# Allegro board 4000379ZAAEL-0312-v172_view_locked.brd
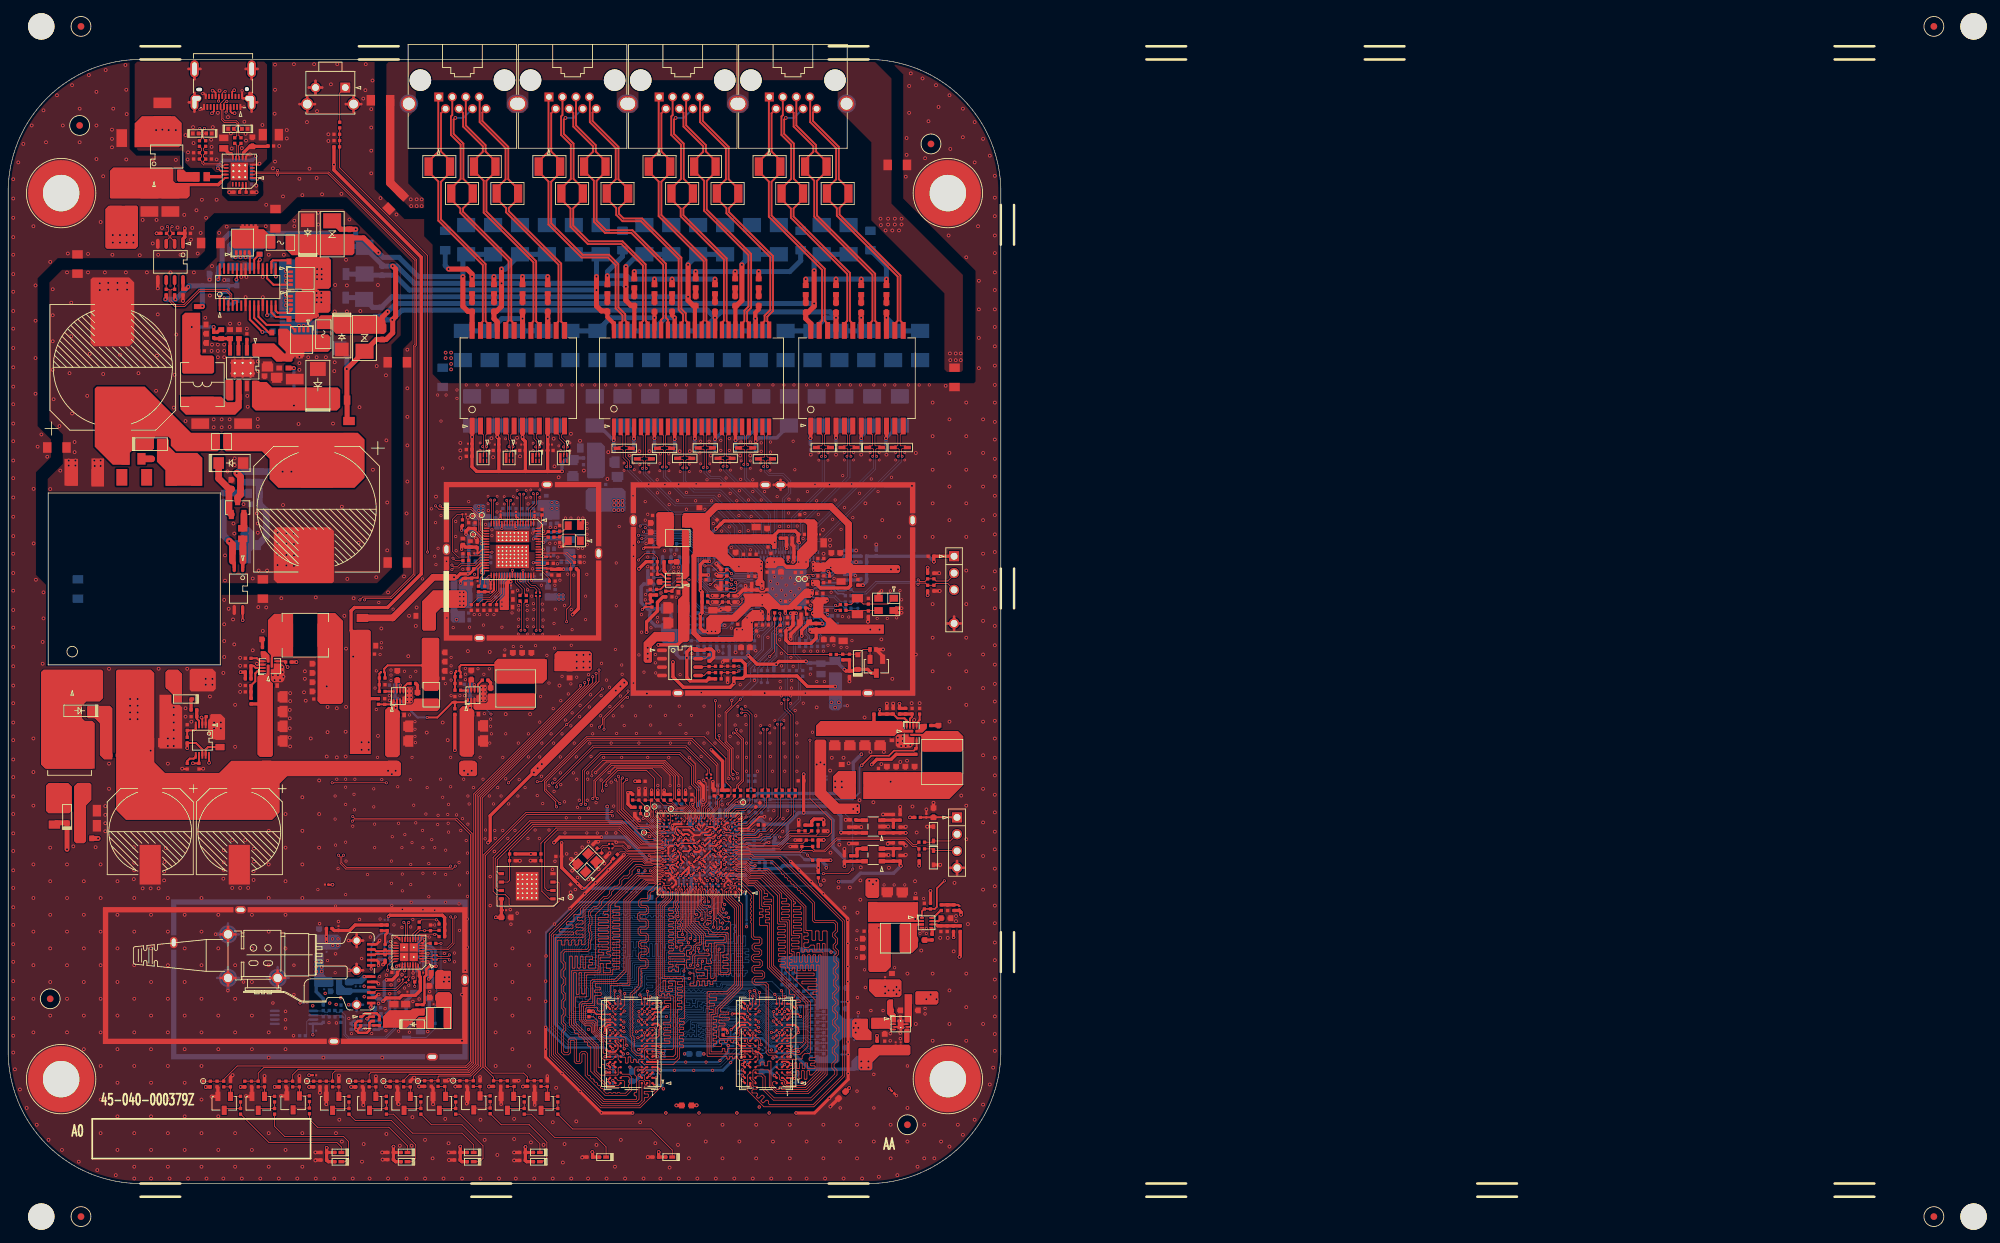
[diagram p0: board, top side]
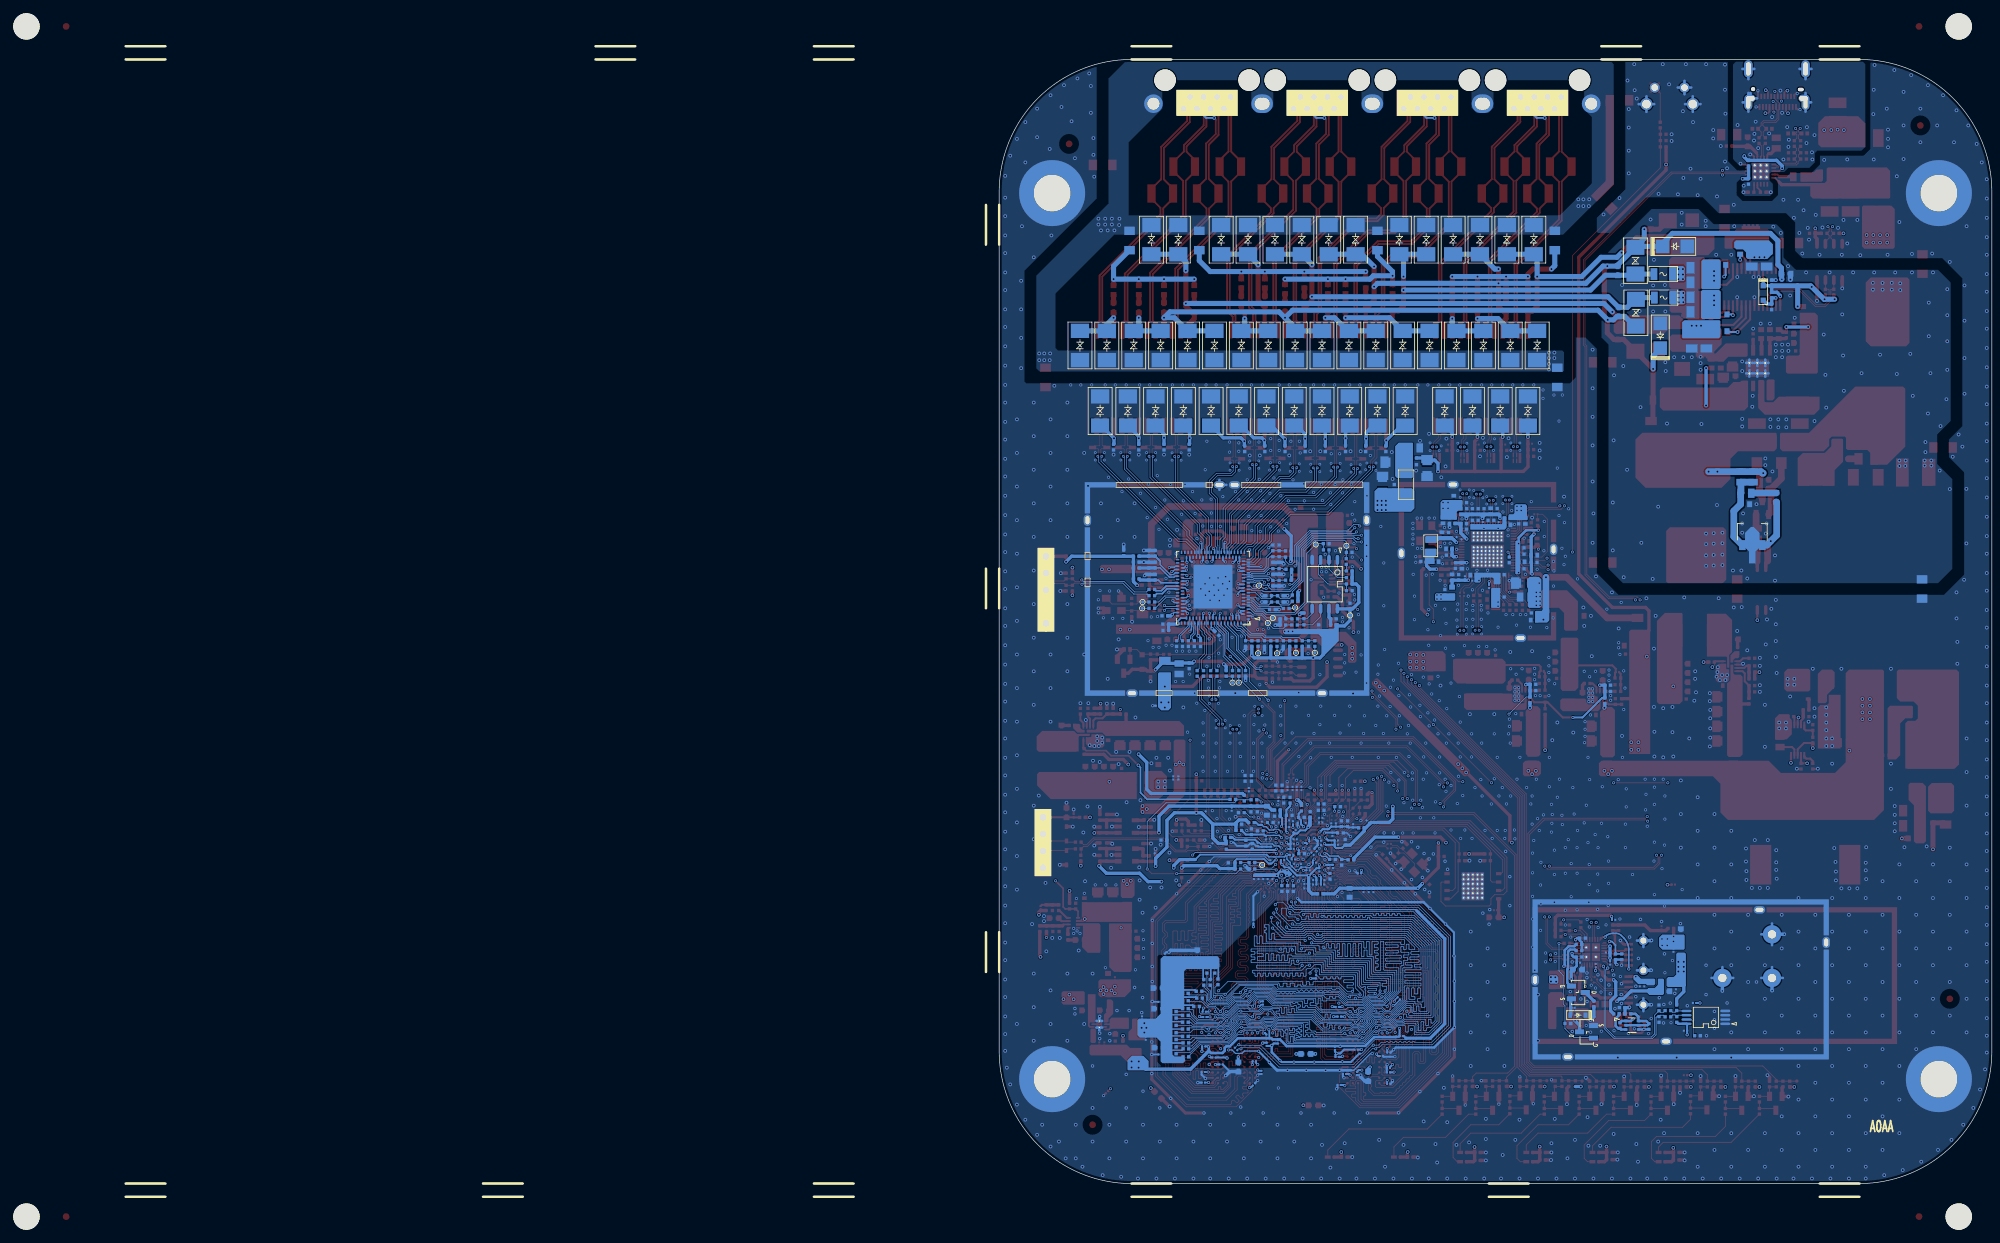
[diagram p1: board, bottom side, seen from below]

Outline 150 x 170 mm; copper layers: TOP, L2, L3, BOTTOM. Coordinates in mm from the lower left corner of the outline.

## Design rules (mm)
constraint set DEFAULT: min track width 0.127
net group DDR_BL0_LDQS: nets DDR_BL0_LDQS_N DDR_BL0_LDQS_P
net group DDR_BL1_UDQS: nets DDR_BL1_UDQS_N DDR_BL1_UDQS_P
net group DDR_BL2_LDQS: nets DDR_BL2_LDQS_N DDR_BL2_LDQS_P
net group DDR_BL3_UDQS: nets DDR_BL3_UDQS_N DDR_BL3_UDQS_P
net group DDR_CK: nets DDR_CK_N DDR_CK_P
net group RXIN_N: nets RXIN1_P RXIN_N
net group RXIN_P: nets RXIN1_N RXIN_P
net group RXOUT+: nets RXOUT+ RXOUTP
net group RXOUT-: nets RXOUT- RXOUTN
net group TXIN_N: nets FXM_P2_TXN TXIN_N
net group TXIN_P: nets FXM_P2_TXP TXIN_P
net group EAR_GND: nets EAR_GND
net group S0RXN: nets N19489844 S0RXN USXGMII1_TD-
net group S0RXP: nets N19489842 S0RXP USXGMII1_TD+
net group S0TXN: nets N19489796 S0TXN USXGMII1_RD-
net group S0TXP: nets N19489794 S0TXP USXGMII1_RD+
net group UART: nets N19665679 N19665693 U0RXD UART0_RX UART0_TX
net group USXGMII0_RD+: nets N17882349 USXGMII0_RD+ USXGMII_TD+_RTL8261BE
net group USXGMII0_RD-: nets N17882351 USXGMII0_RD- USXGMII_TD-_RTL8261BE
net group USXGMII0_TD+: nets N19489360 USXGMII0_TD+ USXGMII_RD+_RTL8261BE
net group USXGMII0_TD-: nets N19489361 USXGMII0_TD- USXGMII_RD-_RTL8261BE

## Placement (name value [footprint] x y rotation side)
C1  10 UF/6.3V  [C0402]  107.97 55.56 0 bottom
C2  0.1 UF/10V  [C0201]  105.73 50.61 180 bottom
C9  10 UF/6.3V  [C0402]  101.35 56.45 180 bottom
C10  10 UF/6.3V  [C0402]  108.2 59.82 90 bottom
C11  10 UF/6.3V  [C0402]  101.35 57.4 180 bottom
C12  10 UF/6.3V  [C0402]  107.25 59.82 90 bottom
C13  10 UF/6.3V  [C0402]  97.35 54.42 90 bottom
C14  10 UF/6.3V  [C0402]  112.84 61.28 90 bottom
C15  0.1 UF/10V  [C0201]  107.82 58.1 270 bottom
C16  10 UF/6.3V  [C0402]  83.19 49.47 180 top
C17  0.1 UF/100V  [C0603]  16 64.77 180 top
C18  10 UF/6.3V  [C0402]  95.82 60.83 0 top
C19  10 UF/6.3V  [C0402]  111.95 56.64 270 bottom
C20  10 UF/6.3V  [C0402]  111 56.64 270 bottom
C21  10 UF/6.3V  [C0402]  85.28 45.53 225 top
C22  10 UF/6.3V  [C0402]  125.12 51.94 0 bottom
C23  10 UF/6.3V  [C0402]  113.79 54.36 180 bottom
C24  0.1 UF/10V  [C0201]  102.11 31.26 270 bottom
C25  0.1 UF/10V  [C0201]  94.16 44.32 270 bottom
C26  0.1 UF/10V  [C0201]  93.45 44.32 270 bottom
C27  0.1 UF/10V  [C0201]  94.95 44.32 270 bottom
C28  0.1 UF/10V  [C0201]  138.75 55.63 90 top
C29  82 PF/50V  [C0402]  28.83 63.12 270 top
C86  0.1 UF/16V  [C0402]  113.92 59.05 270 top
C87  0.1 UF/16V  [C0402]  114.87 59.05 270 top
C89  0.1 UF/16V  [C0402]  117.98 59.05 270 top
C93  0.1 UF/16V  [C0402]  118.94 59.05 270 top
C94  0.1 UF/10V  [C0201]  119.17 15.27 0 bottom
C95  0.01 UF/16V  [C0201]  110.38 16.81 270 bottom
C96  6800 PF/10V  [C0201]  109.58 21.06 270 bottom
C98  0.1 UF/10V  [C0201]  109.63 22.29 90 bottom
C99  4700 PF/10V  [C0201]  117.54 19.05 180 bottom
C100  6800 PF/10V  [C0201]  95.55 46.91 0 bottom
C101  1 UF/6.3V  [C0201]  119.09 20.73 0 bottom
C102  2200 PF/16V  [C0201]  110.15 27.31 90 bottom
C103  1500 PF/16V  [C0201]  119.02 25.98 0 bottom
C104  1500 PF/16V  [C0201]  118.91 25.18 0 bottom
C105  1000 PF/50V  [C0201]  111.44 18.5 0 bottom
C106  2200 PF/16V  [C0201]  91.11 19.81 180 bottom
C110  4700 PF/10V  [C0201]  91.19 16.81 0 bottom
C111  0.1 UF/10V  [C0201]  99.26 20.45 270 bottom
C112  1500 PF/16V  [C0201]  91.19 17.48 0 bottom
C113  1000 PF/50V  [C0201]  98.6 25.25 0 bottom
C114  1500 PF/16V  [C0201]  111.58 39.57 90 bottom
C115  0.01 UF/16V  [C0201]  89.61 28.02 45 bottom
C116  0.1 UF/10V  [C0201]  133.71 13.82 315 top
C117  1 UF/6.3V  [C0201]  104.39 48.06 90 bottom
C136  1 UF/16V  [C0402]  69.66 111 180 top
C137  1 UF/16V  [C0402]  81.92 110.87 0 top
C139  1 UF/16V  [C0402]  128.91 111.38 270 bottom
C140  1 UF/6.3V  [C0201]  92.26 19.28 180 bottom
C141  0.1 UF/10V  [C0201]  95.94 16.64 270 bottom
C142  1 UF/6.3V  [C0201]  116.47 18.01 180 bottom
C143  10 UF/6.3V  [C0603]  125.98 29.57 0 bottom
C144  10 UF/6.3V  [C0603]  120.07 34.6 90 bottom
C145  10 UF/6.3V  [C0603]  125.91 26.44 0 bottom
C146  10 UF/6.3V  [C0603]  125.83 20.55 0 bottom
C148  1 UF/16V  [C0402]  73.72 110.87 180 top
C151  1 UF/16V  [C0402]  77.72 110.87 180 top
C153  0.01 UF/16V  [C0201]  105.79 49.72 180 bottom
C154  0.1 UF/10V  [C0201]  105.61 48.16 135 bottom
C155  0.1 UF/10V  [C0201]  102.36 48.51 180 bottom
C156  1 UF/16V  [C0402]  121.28 111.38 270 bottom
C159  0.1 UF/10V  [C0201]  98.91 26.71 0 bottom
C160  1 UF/16V  [C0402]  132.72 111.38 270 bottom
C161  15 PF/50V  [C0402]  89.98 49.68 315 top
C162  15 PF/50V  [C0402]  88.69 50.99 135 top
C166  10 UF/6.3V  [C0402]  98.3 54.42 270 bottom
C167  10 UF/6.3V  [C0402]  107 57.98 270 bottom
C168  0.1 UF/10V  [C0201]  100.25 47.96 270 bottom
C169  0.01 UF/16V  [C0201]  99.57 47.96 270 bottom
C170  0.1 UF/10V  [C0201]  96.52 54.1 270 bottom
C171  0.1 UF/10V  [C0201]  109.41 46.29 270 bottom
C172  0.01 UF/16V  [C0201]  101.14 45.21 180 bottom
C173  10 UF/6.3V  [C0402]  115.38 48.07 90 bottom
C174  0.1 UF/10V  [C0201]  101.41 55.31 180 bottom
C175  0.1 UF/10V  [C0201]  99.12 54.23 270 bottom
C176  0.1 UF/10V  [C0201]  108.71 46.29 270 bottom
C177  0.01 UF/16V  [C0201]  102.31 45.9 0 bottom
C178  10 UF/6.3V  [C0402]  97.71 51.61 90 bottom
C179  0.1 UF/10V  [C0201]  105.28 52.07 0 bottom
C180  0.1 UF/10V  [C0201]  104.65 54.55 180 bottom
C181  10 UF/6.3V  [C0402]  106.17 55.69 180 bottom
C182  0.01 UF/16V  [C0201]  99.82 54.23 270 bottom
C183  0.01 UF/16V  [C0201]  106.43 59.75 90 bottom
C184  0.1 UF/10V  [C0201]  101.12 45.9 180 bottom
C185  0.01 UF/16V  [C0201]  111.51 46.29 270 bottom
C186  0.1 UF/10V  [C0201]  99.06 51.23 180 bottom
C187  0.1 UF/10V  [C0201]  109.7 52.27 90 bottom
C188  0.01 UF/16V  [C0201]  106.43 53.91 180 bottom
C189  10 UF/6.3V  [C0402]  98.42 53.02 180 bottom
C190  0.1 UF/10V  [C0201]  105.74 46.61 225 bottom
C191  0.01 UF/16V  [C0201]  102.31 45.21 0 bottom
C192  0.1 UF/10V  [C0201]  94.3 54.74 45 bottom
C193  0.1 UF/10V  [C0201]  110.95 51.31 90 bottom
C194  0.01 UF/16V  [C0201]  106.43 54.93 180 bottom
C195  0.1 UF/10V  [C0201]  98.93 19.15 0 bottom
C196  0.01 UF/16V  [C0201]  110.81 46.29 270 bottom
C197  0.01 UF/16V  [C0201]  103.31 51.56 135 bottom
C198  0.01 UF/16V  [C0201]  105.35 53.28 135 bottom
C199  0.1 UF/10V  [C0201]  99.06 51.89 180 bottom
C200  0.1 UF/10V  [C0201]  98.63 14.91 0 bottom
C201  0.01 UF/16V  [C0201]  103.31 47.37 180 bottom
C202  0.01 UF/16V  [C0201]  99.63 52.83 270 bottom
C203  0.01 UF/16V  [C0201]  109.02 48.64 90 bottom
C204  0.1 UF/10V  [C0201]  110.11 46.29 270 bottom
C205  0.01 UF/16V  [C0201]  97.82 16.56 0 bottom
C206  0.01 UF/16V  [C0201]  105.73 51.37 180 bottom
C207  0.01 UF/16V  [C0201]  103.44 54.55 0 bottom
C208  0.1 UF/10V  [C0201]  123.7 61.34 270 bottom
C209  0.01 UF/16V  [C0201]  101.63 51.84 180 bottom
C210  0.01 UF/16V  [C0201]  107.51 54.61 0 bottom
C211  0.1 UF/10V  [C0201]  104.33 59.75 270 bottom
C212  0.01 UF/16V  [C0201]  102.64 49.86 225 bottom
C213  0.01 UF/16V  [C0201]  103.63 44.63 180 bottom
C214  0.1 UF/10V  [C0201]  105.03 59.75 270 bottom
C215  0.01 UF/16V  [C0201]  102.18 50.42 225 bottom
C216  0.01 UF/16V  [C0201]  103.63 45.31 180 bottom
C217  0.1 UF/10V  [C0201]  122.94 61.34 270 bottom
C218  0.01 UF/16V  [C0201]  105.54 49.02 0 bottom
C219  0.01 UF/16V  [C0201]  108.94 50.7 90 bottom
C220  0.1 UF/10V  [C0201]  101.63 47.45 90 bottom
C221  0.1 UF/10V  [C0201]  105.66 59.75 270 bottom
C222  0.01 UF/16V  [C0201]  101.41 54.61 180 bottom
C223  0.1 UF/10V  [C0201]  109.6 50.7 90 bottom
C224  0.1 UF/10V  [C0201]  107.19 48.92 0 bottom
C225  0.1 UF/10V  [C0201]  101.63 51.18 0 bottom
C226  0.01 UF/16V  [C0201]  112.27 59.56 270 bottom
C227  10 UF/6.3V  [C0402]  111.76 51 90 bottom
C228  10 UF/6.3V  [C0402]  99.63 49.02 0 bottom
C229  10 UF/6.3V  [C0402]  104.29 49.88 180 bottom
C230  10 UF/6.3V  [C0402]  111.89 61.28 90 bottom
C231  0.1 UF/10V  [C0201]  110.29 50.7 90 bottom
C232  22 UF/6.3V  [C0603]  126.01 13.39 225 top
C233  1000 PF/2KV  [C1206-0160]  134.37 154.05 0 top
C234  1000 PF/2KV  [C1206-0160]  130.3 142.62 90 bottom
C235  10 UF/6.3V  [C0402]  104.33 55.37 180 bottom
C236  10 UF/6.3V  [C0402]  111.89 53.21 90 bottom
C237  1000 PF/2KV  [C1206-0160]  66.04 142.62 90 bottom
C238  1000 PF/2KV  [C1206-0160]  58.55 148.46 225 top
C239  10 UF/6.3V  [C0402]  112.73 51.49 270 bottom
C241  1000 PF/2KV  [C1206-0160]  56.26 163.83 180 top
C242  0.01 UF/100V  [C0603]  81.53 132.59 90 top
C243  0.01 UF/100V  [C0603]  77.72 132.59 90 top
C244  0.01 UF/100V  [C0603]  73.41 132.59 90 top
C245  0.01 UF/100V  [C0603]  70.1 132.59 90 top
C246  0.01 UF/100V  [C0603]  132.72 132.46 90 top
C247  0.01 UF/100V  [C0603]  128.91 132.46 90 top
C248  0.01 UF/100V  [C0603]  125.09 132.46 90 top
C249  0.01 UF/100V  [C0603]  120.52 132.46 90 top
C250  0.01 UF/100V  [C0603]  113.41 133.48 90 top
C251  0.01 UF/100V  [C0603]  109.86 133.48 90 top
C252  0.01 UF/100V  [C0603]  94.61 133.48 90 top
C253  0.01 UF/100V  [C0603]  103.89 133.48 90 top
C254  0.01 UF/100V  [C0603]  100.33 132.59 90 top
C255  1 UF/6.3V  [C0402]  33.27 132.59 270 bottom
C256  0.01 UF/100V  [C0603]  97.66 132.59 90 top
C257  0.01 UF/100V  [C0603]  106.81 132.59 90 top
C258  0.01 UF/100V  [C0603]  90.55 132.59 90 top
C259  1000 PF/2KV  [C1206-0160]  143 121.92 270 top
C260  1000 PF/2KV  [C1206-0160]  40.39 145.92 90 top
C261  1000 PF/2KV  [C1206-0160]  58.8 124.21 0 top
C262  1000 PF/2KV  [C1206-0160]  58.8 93.92 0 top
C263  1000 PF/2KV  [C1206-0160]  38.48 89.92 90 top
C264  1000 PF/2KV  [C1206-0160]  30.61 142.24 180 top
C265  1000 PF/2KV  [C1206-0160]  10.54 89.92 270 bottom
C266  1000 PF/2KV  [C1206-0160]  7.37 111.32 180 top
C267  1000 PF/2KV  [C1206-0160]  10.48 139.06 90 top
C270  0.1 UF/10V  [C0201]  105.54 61.59 90 top
C271  0.1 UF/10V  [C0201]  106.24 61.59 90 top
C272  2.2 UF/6.3V  [C0402]  111.81 47.57 0 bottom
C276  1 UF/16V  [C0402]  125.09 111.38 270 bottom
C277  0.1 UF/10V  [C0201]  74.99 41.34 0 top
C278  10 UF/6.3V  [C0603]  75.25 40.26 0 top
C279  1 UF/16V  [C0402]  97.66 111.12 270 bottom
C280  1 UF/16V  [C0402]  91.57 111.12 270 bottom
C281  1 UF/16V  [C0402]  100.71 111.12 270 bottom
C282  1 UF/16V  [C0402]  94.61 111.12 270 bottom
C283  1 UF/16V  [C0402]  109.86 111.12 270 bottom
C284  1 UF/16V  [C0402]  103.76 111.12 270 bottom
C285  1 UF/16V  [C0402]  112.9 111.12 270 bottom
C286  1 UF/16V  [C0402]  106.81 111.12 270 bottom
C288  1000 PF/2KV  [C1206-0160]  119.76 142.62 90 bottom
C293  1000 PF/2KV  [C1206-0160]  65.66 121.92 270 bottom
C294  1000 PF/2KV  [C1206-0160]  92.84 142.62 90 bottom
C600  0.1 UF/10V  [C0201]  60.32 30.58 225 top
C601  0.1 UF/10V  [C0201]  59.82 31.05 225 top
C602  0.01 UF/16V  [C0201]  59.84 32.96 90 bottom
C603  0.01 UF/50V  [C0402]  58.4 31.94 180 top
C606  0.1 UF/10V  [C0201]  62.47 31.9 0 top
C607  0.1 UF/10V  [C0201]  49.91 38.67 90 top
C608  0.1 UF/10V  [C0201]  58.07 34.92 0 bottom
C609  0.1 UF/10V  [C0201]  64.51 33.86 180 top
C610  0.1 UF/10V  [C0201]  64.51 34.54 180 top
C611  6.2 PF/50V  [C0402]  62.39 34.26 180 bottom
C612  0.1 UF/50V  [C0402]  55.86 26.61 180 bottom
C613  1 UF/6.3V  [C0201]  52.52 30.07 270 bottom
C614  0.1 UF/10V  [C0201]  53.19 30.07 270 bottom
C616  0.1 UF/10V  [C0201]  46.28 23.11 0 bottom
C619  1 UF/50V  [C0805]  58.29 26.34 90 top
C620  2.2 UF/50V  [C0805]  60.07 26.34 90 top
C621  4.7 PF/50V  [C0402]  61.77 26.63 90 top
C623  10 UF/6.3V  [C0603]  49.42 29.08 180 bottom
C624  0.1 UF/10V  [C0201]  60.33 28.77 90 top
C625  10 UF/6.3V  [C0603]  62.61 32.35 180 bottom
C626  0.1 UF/10V  [C0201]  62.45 33.4 180 bottom
C631  10 UF/6.3V  [C0603]  64.35 29.89 180 top
C632  0.1 UF/10V  [C0201]  47.74 29.63 270 bottom
C633  0.1 UF/10V  [C0201]  46.29 16.38 0 top
C634  0.1 UF/10V  [C0201]  126.1 72.26 0 bottom
C635  0.1 UF/10V  [C0201]  44.92 27.31 0 bottom
C636  0.1 UF/10V  [C0201]  48.12 45.21 180 top
C637  0.1 UF/10V  [C0201]  57.15 39.88 180 bottom
C638  10 UF/6.3V  [C0603]  64.41 28.13 180 top
C639  0.1 UF/10V  [C0201]  64.52 27.11 180 top
C640  0.1 UF/10V  [C0201]  57.68 33.36 270 bottom
C643  10 UF/6.3V  [C0603]  46.99 37.78 90 bottom
C644  0.1 UF/10V  [C0201]  48.11 35.29 270 bottom
C719  0.1 UF/16V  [C0402]  27.11 143.7 0 top
C720  0.1 UF/16V  [C0402]  26.42 134.81 90 top
C810  0.1 UF/16V  [C0402]  49.66 158.69 180 top
C843  0.1 UF/100V  [C0603]  34.23 118.94 0 top
C844  2.2 UF/100V  [C1210]  43.31 120.27 90 top
C845  1 UF/100V  [C1206]  40.58 120.65 90 top
C846  0.1 UF/100V  [C0603]  38.73 121.41 90 top
C847  680 PF/50V  [C0402]  31.05 128.33 270 top
C848  0.1 UF/16V  [C0402]  29.21 125.92 0 top
C849  22 UF/10V  [C0603]  29.21 127.13 0 top
C850  22 UF/10V  [C0603]  29.21 128.52 0 top
C851  1 UF/100V  [C1206]  39.18 124.78 270 top
C852  1 UF/16V  [C0402]  36.07 128.08 90 top
C911  1000 PF/50V  [C0402]  54.93 80.07 0 top
C922  0.1 UF/10V  [C0201]  117.6 51.64 315 bottom
C925  10 UF/6.3V  [C0603]  139.83 56.07 90 top
C926  0.1 UF/10V  [C0201]  126.31 49.78 45 bottom
C927  0.1 UF/10V  [C0201]  118.97 56.11 135 bottom
C928  0.1 UF/10V  [C0201]  132.51 30.96 90 top
C944  10 UF/6.3V  [C0603]  136.78 26.19 0 top
C946  10 UF/6.3V  [C0603]  134.11 26.19 0 top
C947  10 UF/6.3V  [C0603]  132.46 23.32 270 top
C948  0.1 UF/10V  [C0201]  134.11 21.11 90 top
C949  0.1 UF/10V  [C0201]  134.87 21.11 90 top
C956  470 PF/50V  [C0201]  89.25 22.3 180 bottom
C957  470 PF/50V  [C0201]  107.9 21.42 270 bottom
C958  1000 PF/50V  [C0201]  119.17 16.87 0 bottom
C959  1000 PF/50V  [C0201]  96.06 20.24 0 bottom
C960  3300 PF/16V  [C0201]  111.5 14.99 135 bottom
C961  3300 PF/16V  [C0201]  91.12 15.07 180 bottom
C971  10 UF/6.3V  [C0603]  103.66 19.6 0 bottom
C972  10 UF/6.3V  [C0603]  94.25 16.19 270 bottom
C973  10 UF/6.3V  [C0603]  102.51 11.81 180 top
C974  10 UF/6.3V  [C0603]  113.85 17.61 270 bottom
C976  0.1 UF/10V  [C0201]  128.42 25.03 90 bottom
C977  0.1 UF/10V  [C0201]  127.86 21.98 270 bottom
C978  470 PF/50V/10%  [C0201]  125.68 27.48 0 bottom
C979  1 UF/6.3V  [C0201]  124.97 34.52 90 bottom
C980  1 UF/6.3V  [C0201]  125.68 19.52 0 bottom
C981  0.1 UF/16V  [C0402]  49.66 157.73 0 top
C1002  0.22 UF/6.3V  [C0402]  134.79 51.09 90 top
C1003  1 UF/6.3V  [C0402]  134.79 49.19 90 top
C1004  1 UF/6.3V  [C0402]  119.81 60.91 180 top
C1005  1 UF/6.3V  [C0402]  126.36 49.15 90 top
C1006  0.022 UF/25V  [C0402]  127.32 49.15 90 top
C1007  0.22 UF/6.3V  [C0402]  134.79 55.38 90 top
C1008  1 UF/6.3V  [C0402]  134.79 53.48 90 top
C1009  1 UF/6.3V  [C0402]  127.04 53.48 90 top
C1010  1 UF/6.3V  [C0402]  128.05 53.48 90 top
C1011  0.01 UF/50V  [C0402]  127.67 55 180 top
C1012  0.1 UF/10V  [C0201]  114.87 56.63 270 bottom
C1013  0.01 UF/16V  [C0201]  105.6 54.55 90 bottom
C1014  0.01 UF/16V  [C0201]  110.3 54.48 90 bottom
C8557  1 UF/50V  [C0805]  32.58 157.35 90 top
C8558  0.1 UF/50V  [C0603]  36.89 157.54 90 top
C8559  10 UF/50V  [C1210]  24.51 148.4 270 top
C8560  10 UF/50V  [C1210]  23.3 162.05 90 top
C8561  10 UF/50V  [C1210]  21.34 148.4 270 top
C8562  10 UF/50V  [C1210]  18.54 158.12 180 top
C8564  10 UF/50V  [C1210]  22.35 69.22 0 top
C8565  1 UF/50V  [C0805]  22.35 66.67 0 top
C8566  0.22 UF/16V  [C0402]  27.05 63.12 270 top
C8567  10 UF/50V  [C1210]  22.35 72.52 0 top
C8568  4.7 UF/25V  [C0805]  32 66.8 90 top
C8569  220 UF/100V  [CES-1800-P-1750-S]  15.81 123.44 90 top
C8571  0.1 UF/100V  [C0603]  34.42 106.43 180 top
C8572  0.1 UF/16V  [C0402]  33.27 136.21 270 bottom
C8573  0.1 UF/100V  [C0603]  31.11 137.6 180 bottom
C8574  0.1 UF/100V  [C0603]  56.52 128.33 90 top
C8575  0.1 UF/100V  [C0603]  56.39 131.83 90 bottom
C8576  0.1 UF/100V  [C0603]  56.52 138.05 270 bottom
C8577  0.1 UF/100V  [C0603]  51.56 143.64 270 top
C8578  220 PF/100V  [C0805]  36.07 106.87 270 bottom
C8580  100 PF/100V  [C0603]  22.35 109.6 180 top
C8581  2.2 UF/100V  [C1210]  29.02 113.54 90 top
C8582  0.22 UF/25V  [C0603]  32.58 103.76 90 bottom
C8583  2.2 UF/100V  [C1210]  35.5 113.54 90 top
C8584  220 UF/100V  [CES-1800-P-1750-S]  46.61 101.98 270 top
C8585  220 UF/63V  [CES-1250-P-1350-L]  21.46 53.21 270 top
C8586  220 UF/63V  [CES-1250-P-1350-L]  34.92 53.21 270 top
C8595  330 PF/50V  [C0402]  30.29 155.89 0 top
C8596  330 PF/50V  [C0402]  28.45 155.89 180 top
CE19  0.1 UF/16V  [C0402]  31.56 15.05 270 top
CE20  0.1 UF/16V  [C0402]  33.59 15.05 90 top
CE21  0.1 UF/16V  [C0402]  38.73 15.05 90 top
CE22  0.1 UF/16V  [C0402]  36.77 15.05 270 top
CE23  0.1 UF/16V  [C0402]  44.01 15.05 90 top
CE24  0.1 UF/16V  [C0402]  41.97 15.05 270 top
CE25  0.1 UF/16V  [C0402]  81.47 15.11 90 top
CE26  0.1 UF/16V  [C0402]  79.5 15.11 270 top
CE27  0.1 UF/16V  [C0402]  74.42 15.11 270 top
CE28  0.1 UF/16V  [C0402]  76.45 15.11 90 top
CE29  0.1 UF/16V  [C0402]  47.12 15.05 270 top
CE30  0.1 UF/16V  [C0402]  49.97 15.05 90 top
CE31  0.1 UF/16V  [C0402]  55.56 15.05 90 top
CE32  0.1 UF/16V  [C0402]  58.74 15.05 270 top
CE33  0.1 UF/16V  [C0402]  60.77 15.05 90 top
CE34  0.1 UF/16V  [C0402]  53.53 15.05 270 top
CE35  0.1 UF/16V  [C0402]  65.98 15.11 90 top
CE36  0.1 UF/16V  [C0402]  69.28 15.11 270 top
CE37  0.1 UF/16V  [C0402]  71.31 15.11 90 top
CE38  0.1 UF/16V  [C0402]  63.94 15.11 270 top
CE72  0.1 UF/16V  [C0402]  47.69 4.7 180 top
CE73  0.1 UF/16V  [C0402]  47.69 3.56 180 top
CE74  0.1 UF/16V  [C0402]  57.78 4.7 180 top
CE75  0.1 UF/16V  [C0402]  97.85 4 180 top
CE76  0.1 UF/16V  [C0402]  87.88 4 180 top
CE77  0.1 UF/16V  [C0402]  57.78 3.62 180 top
CE78  0.1 UF/16V  [C0402]  67.88 3.56 180 top
CE79  0.1 UF/16V  [C0402]  67.88 4.7 180 top
CE80  0.1 UF/16V  [C0402]  77.72 3.49 180 top
CE81  0.1 UF/16V  [C0402]  77.72 4.7 180 top
D3  SCS4148LWS-C  [DOS-SOD-323L-SECOS]  34.54 134.68 270 bottom
D65  BV-SMBJ58C2  [VARS-SMB-BENCENT]  70.1 116.84 270 bottom
D66  BV-SMBJ58C2  [VARS-SMB-BENCENT]  74.3 116.84 270 bottom
D67  BV-SMBJ58C2  [VARS-SMB-BENCENT]  78.49 116.84 270 bottom
D68  BV-SMBJ58C2  [VARS-SMB-BENCENT]  82.68 116.84 270 bottom
D69  BV-SMBJ58C2  [VARS-SMB-BENCENT]  122.17 116.84 270 bottom
D70  BV-SMBJ58C2  [VARS-SMB-BENCENT]  130.56 116.84 270 bottom
D71  BV-SMBJ58C2  [VARS-SMB-BENCENT]  134.75 116.84 270 bottom
D72  BV-SMBJ58C2  [VARS-SMB-BENCENT]  126.36 116.84 270 bottom
D73  BV03C-H  [VARS-SOD-323-BENCENT]  134.81 111.32 0 top
D74  BV03C-H  [VARS-SOD-323-BENCENT]  130.94 111.32 0 top
D75  BV03C-H  [VARS-SOD-323-BENCENT]  127.06 111.32 0 top
D76  BV03C-H  [VARS-SOD-323-BENCENT]  123.19 111.32 0 top
D77  BV-SMBJ58C2  [VARS-SMB-BENCENT]  88.65 116.84 270 bottom
D78  BV-SMBJ58C2  [VARS-SMB-BENCENT]  97.03 116.84 270 bottom
D79  BV-SMBJ58C2  [VARS-SMB-BENCENT]  68.71 126.75 270 bottom
D80  BV-SMBJ58C2  [VARS-SMB-BENCENT]  81.41 142.75 90 bottom
D81  BV-SMBJ58C2  [VARS-SMB-BENCENT]  80.9 126.75 270 bottom
D82  BV-SMBJ58C2  [VARS-SMB-BENCENT]  73.28 142.75 90 bottom
D83  BV-SMBJ58C2  [VARS-SMB-BENCENT]  125.6 126.75 270 bottom
D84  BV-SMBJ58C2  [VARS-SMB-BENCENT]  117.47 126.75 270 bottom
D85  BV-SMBJ58C2  [VARS-SMB-BENCENT]  137.79 126.75 270 bottom
D86  BV-SMBJ58C2  [VARS-SMB-BENCENT]  127 142.75 90 bottom
D87  BV-SMBJ58C2  [VARS-SMB-BENCENT]  101.22 116.84 270 bottom
D88  BV-SMBJ58C2  [VARS-SMB-BENCENT]  92.84 116.84 270 bottom
D89  BV03C-H  [VARS-SOD-323-BENCENT]  102.23 109.66 0 top
D90  BV03C-H  [VARS-SOD-323-BENCENT]  99.19 111.19 0 top
D91  BV03C-H  [VARS-SOD-323-BENCENT]  96.14 109.6 0 top
D92  BV03C-H  [VARS-SOD-323-BENCENT]  93.09 111.19 0 top
D93  BV-SMBJ58C2  [VARS-SMB-BENCENT]  105.41 116.84 270 bottom
D94  BV-SMBJ58C2  [VARS-SMB-BENCENT]  113.79 116.84 270 bottom
D95  BV-SMBJ58C2  [VARS-SMB-BENCENT]  117.98 116.84 270 bottom
D96  BV-SMBJ58C2  [VARS-SMB-BENCENT]  109.6 116.84 270 bottom
D97  BV03C-H  [VARS-SOD-323-BENCENT]  114.43 109.6 0 top
D98  BV03C-H  [VARS-SOD-323-BENCENT]  111.44 111.25 0 top
D99  BV03C-H  [VARS-SOD-323-BENCENT]  108.33 109.66 0 top
D100  BV03C-H  [VARS-SOD-323-BENCENT]  105.35 111.25 0 top
D101  BV-SMBJ58C2  [VARS-SMB-BENCENT]  112.39 142.75 90 bottom
D102  BV-SMBJ58C2  [VARS-SMB-BENCENT]  101.22 126.75 270 bottom
D103  BV-SMBJ58C2  [VARS-SMB-BENCENT]  113.41 126.75 270 bottom
D104  BV-SMBJ58C2  [VARS-SMB-BENCENT]  108.33 142.75 90 bottom
D105  BV-SMBJ58C2  [VARS-SMB-BENCENT]  89.03 126.75 270 bottom
D106  BV-SMBJ58C2  [VARS-SMB-BENCENT]  100.2 142.75 90 bottom
D107  BV-SMBJ58C2  [VARS-SMB-BENCENT]  93.09 126.75 270 bottom
D108  BV-SMBJ58C2  [VARS-SMB-BENCENT]  89.53 142.75 90 bottom
D109  AZ5423-01F.R7GR  [VARS-DFN1006P2E-AMAZING]  33.66 159.51 0 top
D110  AZ5423-01F.R7GR  [VARS-DFN1006P2E-AMAZING]  35.75 159.51 180 top
D111  BV-SMBJ58C2  [VARS-SMB-BENCENT]  76.83 126.75 90 bottom
D112  BV-SMBJ58C2  [VARS-SMB-BENCENT]  72.77 126.75 90 bottom
D113  BV-SMBJ58C2  [VARS-SMB-BENCENT]  77.34 142.75 270 bottom
D114  BV-SMBJ58C2  [VARS-SMB-BENCENT]  69.22 142.75 270 bottom
D115  BV-SMBJ58C2  [VARS-SMB-BENCENT]  133.73 126.75 90 bottom
D116  BV-SMBJ58C2  [VARS-SMB-BENCENT]  129.67 126.75 90 bottom
D117  BV-SMBJ58C2  [VARS-SMB-BENCENT]  121.54 126.75 90 bottom
D118  BV-SMBJ58C2  [VARS-SMB-BENCENT]  122.94 142.75 270 bottom
D119  BV-SMBJ58C2  [VARS-SMB-BENCENT]  109.35 126.75 90 bottom
D120  BV-SMBJ58C2  [VARS-SMB-BENCENT]  116.46 142.75 270 bottom
D121  BV-SMBJ58C2  [VARS-SMB-BENCENT]  105.28 126.75 90 bottom
D122  BV-SMBJ58C2  [VARS-SMB-BENCENT]  104.27 142.75 270 bottom
D123  BV-SMBJ58C2  [VARS-SMB-BENCENT]  97.16 126.75 90 bottom
D124  BV-SMBJ58C2  [VARS-SMB-BENCENT]  84.96 126.75 90 bottom
D125  BV-SMBJ58C2  [VARS-SMB-BENCENT]  96.14 142.75 270 bottom
D126  BV-SMBJ58C2  [VARS-SMB-BENCENT]  85.47 142.75 270 bottom
D127  AZ5423-01F.R7GR  [VARS-DFN1006P2E-AMAZING]  30.35 158.81 180 top
D128  AZ5423-01F.R7GR  [VARS-DFN1006P2E-AMAZING]  28.32 158.81 0 top
D600  SCS4148LWS-C  [DOS-SOD-323-PANJIT]  61.21 24.09 0 top
D601  SCS4148LWS-C  [DOS-SOD-323-PANJIT]  62.55 25.46 0 bottom
D802  LTST-T180TGKT-IM  [LEDS-LTST-T180]  100 4 0 top
D803  LTST-T180TGKT-IM  [LEDS-LTST-T180]  50 4.7 0 top
D804  LTST-T180KEKT-IM  [LEDS-LTST-T180]  60 3.3 0 top
D805  LTST-T180UBKT-IM  [LEDS-LTST-T180]  90 4 0 top
D806  LTST-T180TGKT-IM  [LEDS-LTST-T180]  60 4.7 0 top
D807  BAT54HT1-TH-WS  [DOS-SOD-323-WILLAS]  8.89 55.63 90 top
D808  SS30100HE/100V/3A  [DOS-SOD-123HE-PANJIT]  21.59 111.82 0 top
D809  P6SMBJ58CA  [VARS-SMB-PANJIT]  53.85 127.89 90 top
D810  LTST-T180KEKT-IM  [LEDS-LTST-T180]  50 3.3 0 top
D811  P6SMBJ58CA  [VARS-SMB-PANJIT]  53.78 131.7 90 bottom
D812  BR210_R1_00001  [DOS-SMA-PANJIT]  50.1 128.21 90 bottom
D813  P6SMBJ58CA  [VARS-SMB-PANJIT]  53.85 139.57 270 bottom
D814  P6SMBJ58CA  [VARS-SMB-PANJIT]  48.96 143.57 270 top
D815  1N4148WS  [DOS-SOD-323-GRANDE]  26.67 73.28 180 top
D816  SD101AW/60V/2A  [DOS-SOD-123-PANJIT]  10.79 71.5 180 top
D817  SZAF24A  [DOS-SMA-FL-LRC]  33.66 108.97 0 top
D818  TL431AIPK  [SOT-89-3L-RAC-TI]  36.2 98.55 180 bottom
D819  BR210_R1_00001  [DOS-SMA-PANJIT]  45.28 143.83 90 top
D820  BR210_R1_00001  [DOS-SMA-PANJIT]  47.88 141.73 180 bottom
D821  BR210_R1_00001  [DOS-SMA-PANJIT]  50.42 128.02 270 top
D822  LTST-T180TGKT-IM  [LEDS-LTST-T180]  70 4.7 0 top
D823  LTST-T180KEKT-IM  [LEDS-LTST-T180]  70 3.3 0 top
D824  LTST-T180TGKT-IM  [LEDS-LTST-T180]  80 4.7 0 top
D825  LTST-T180KEKT-IM  [LEDS-LTST-T180]  80 3.3 0 top
D903  PJGBLC24C  [VARS-SOD-323-PANJIT]  139.83 49.28 270 top
D904  PJGBLC24C  [VARS-SOD-323-PANJIT]  139.83 52.9 90 top
E1C1  22 UF/6.3V  [C0805]  87.25 111.25 180 bottom
E1C2  22 UF/6.3V  [C0805]  70.48 88.71 0 bottom
E1C14  1000 PF/25V  [C0402]  69.66 109.98 180 top
E1C16  100 UF/6.3V  [C1206]  85.34 108.2 270 bottom
E1C21  0.1 UF/16V  [C0402]  87.38 108.71 180 bottom
E1C22  220 UF/4V  [C1206]  90.42 109.09 0 bottom
E1C23  0.1 UF/16V  [C0402]  90.3 105.28 90 bottom
E1C24  22 UF/6.3V  [C1206]  92.08 105.66 90 bottom
E1C29  220 UF/4V  [C1206]  70.68 90.81 0 bottom
E1C30  10 UF/10V  [MLCC-0120X0070]  69.85 96.71 90 top
E1C31  10 UF/10V  [MLCC-0120X0070]  75.77 87.18 0 top
E1C32  0.1 UF/16V  [C0402]  75.82 89.47 180 top
E1C33  10 UF/10V  [MLCC-0120X0070]  68.71 97.09 90 top
E1C34  10 UF/10V  [MLCC-0120X0070]  75.82 88.33 0 top
E1C35  10 UF/10V  [MLCC-0120X0070]  83.19 92.46 270 top
E1C36  10 UF/10V  [MLCC-0120X0070]  82.02 95.99 0 bottom
E1C37  0.1 UF/16V  [C0402]  82.14 92.46 90 top
E1C38  0.1 UF/16V  [C0402]  69.09 91.12 90 top
E1C39  1000 PF/50V  [C0201]  79.54 101.34 90 top
E1C40  1000 PF/50V  [C0201]  76.73 101.33 90 top
E1C41  1000 PF/50V  [C0201]  74.42 101.41 90 top
E1C42  0.1 UF/16V  [C0402]  77.62 101.63 270 bottom
E1C43  0.1 UF/16V  [C0402]  79.35 101.63 270 bottom
E1C44  0.1 UF/16V  [C0402]  78.49 101.63 270 bottom
E1C45  1 UF/6.3V  [C0402]  76.73 101.63 90 bottom
E1C46  1 UF/6.3V  [C0402]  74.75 101.66 90 bottom
E1C47  10 UF/10V  [MLCC-0120X0070]  75.73 101.68 270 bottom
E1C48  0.1 UF/16V  [C0402]  79.81 102.98 0 bottom
E1C49  10 UF/10V  [MLCC-0120X0070]  81.31 103.56 270 bottom
E1C50  0.1 UF/16V  [C0402]  70.04 91.12 90 top
E1C51  0.1 UF/16V  [C0402]  70.87 96.58 270 top
E1C52  0.1 UF/16V  [C0402]  81.99 95.03 180 bottom
E1C53  1000 PF/50V  [C0201]  75.97 90.31 90 bottom
E1C54  1000 PF/50V  [C0201]  70.93 91.38 90 top
E1C55  1000 PF/50V  [C0201]  70.68 95.31 0 top
E1C56  1000 PF/50V  [C0201]  81.71 94.8 180 top
E1C57  1000 PF/50V  [C0201]  75.74 90.43 180 top
E1C58  1000 PF/50V  [C0201]  81.38 92.77 90 top
E1C59  1000 PF/50V  [C0201]  74.52 99.8 90 bottom
E1C60  1000 PF/50V  [C0201]  76.91 99.8 90 bottom
E1C61  0.1 UF/16V  [C0402]  77.62 99.88 270 bottom
E1C62  0.1 UF/16V  [C0402]  76.12 99.88 270 bottom
E1C63  0.1 UF/16V  [C0402]  75.26 99.88 270 bottom
E1C64  1 UF/6.3V  [C0402]  78.49 99.88 90 bottom
E1C65  10 UF/10V  [MLCC-0120X0070]  73.18 99.62 0 bottom
E1C66  0.1 UF/16V  [C0402]  71.5 100.2 90 bottom
E1C67  10 UF/10V  [MLCC-0120X0070]  70.48 100.2 90 bottom
E1C68  10 UF/10V  [MLCC-0120X0070]  71.06 94.04 0 bottom
E1C69  10 UF/10V  [MLCC-0120X0070]  80.09 93.45 90 bottom
E1C70  0.1 UF/16V  [C0402]  71.12 95.19 180 bottom
E1C71  0.1 UF/16V  [C0402]  71.12 92.96 180 bottom
E1C72  0.1 UF/16V  [C0402]  81.05 93.45 270 bottom
E1C73  0.1 UF/16V  [C0402]  71.12 96.14 180 bottom
E1C74  1000 PF/50V  [C0201]  73.15 90.61 0 top
E1C75  1000 PF/50V  [C0201]  73.15 89.98 0 top
E1C76  1000 PF/50V  [C0201]  81.05 97.59 135 bottom
E1C77  0.1 UF/16V  [C0402]  82.09 98.05 270 bottom
E1C78  10 UF/10V  [MLCC-0120X0070]  83.08 98.05 270 bottom
E1C79  0.1 UF/16V  [C0402]  85.85 94.09 180 bottom
E1C80  10 UF/10V  [MLCC-0120X0070]  84.05 94.06 0 bottom
E1C81  1000 PF/50V  [C0201]  79.96 97.59 315 bottom
E1C82  0.1 UF/16V  [C0402]  79.81 98.96 0 bottom
E1C83  22 UF/6.3V  [C0402]  79.81 99.8 180 bottom
E1C84  0.1 UF/16V  [C0402]  81.97 100.26 90 bottom
E1C85  10 UF/10V  [MLCC-0120X0070]  82.93 100.31 90 bottom
E1C86  10 UF/10V  [MLCC-0120X0070]  69.22 85.22 180 bottom
E1C87  1 UF/6.3V  [C0402]  69.15 86.3 0 bottom
E1C88  0.1 UF/16V  [C0402]  69.6 99.5 90 top
E1C89  0.1 UF/16V  [C0402]  70.55 99.5 270 top
E1C90  10 UF/10V  [MLCC-0120X0070]  69.15 95 0 bottom
E1C91  1 UF/6.3V  [C0402]  69.91 92.96 180 top
E1C92  0.1 UF/16V  [C0402]  69.15 93.92 180 bottom
E1C93  1000 PF/50V  [C0201]  78.27 91.16 0 bottom
E1C94  0.1 UF/16V  [C0402]  74.12 92.08 180 bottom
E1C95  10 UF/10V  [MLCC-0120X0070]  78.34 92.01 180 bottom
E1C96  1 UF/6.3V  [C0402]  74.12 88.7 180 bottom
E1C97  1000 PF/50V  [C0201]  79.62 91.59 90 bottom
E1C98  0.1 UF/16V  [C0402]  80.57 91.67 90 bottom
E1C99  10 UF/10V  [MLCC-0120X0070]  81.56 91.67 270 bottom
E1C100  1 UF/6.3V  [C0402]  82.65 89.41 90 bottom
E1C149  68 PF/16V  [C0201]  69.72 111.89 180 top
E1C150  68 PF/16V  [C0201]  81.92 111.76 0 top
E1C151  68 PF/16V  [C0201]  77.79 111.76 180 top
E1C152  68 PF/16V  [C0201]  73.79 111.76 180 top
E1FB1  HCB1005KF-121T15  [FILTS-0402]  81.1 100.26 270 bottom
E1L1  2.7 nH/850mA  [L0402]  87.38 109.73 180 bottom
E1L2  PBY321611T-601Y-N  [FILTS-PBY321611T]  88.52 105.66 90 bottom
E1L3  HCB1005KF-121T15  [FILTS-0402]  73.2 100.61 0 bottom
E1L4  1 uH/2.61A Isat  [LS-WIP2016]  84.79 96.45 90 bottom
E1L5  PBY160808T-101Y-N  [FILTS-0603]  81.56 89.51 90 bottom
E1L6  PBY160808T-101Y-N  [FILTS-0603]  74.73 90.38 90 bottom
E1LP1  HCB1005KF-121T15  [FILTS-0402]  80.24 101.63 270 bottom
E1R1  10 OHM  [R0402]  82.04 98.61 180 top
E1R2  10 OHM  [R0402]  82.04 97.74 180 top
E1R3  4.7 K  [R0402]  68.64 99.95 90 top
E1R5  2.49 K  [R0402]  80.69 101.54 270 top
E1R12  1 K  [R0402]  86 93.93 0 top
E1R13  1 K  [R0402]  86 94.82 0 top
E1R14  10 K  [R0402]  81.94 93.81 180 top
E1R15  10 K  [R0402]  72.92 94.32 90 bottom
E1R20  10 K  [R0402]  69.15 95.25 180 top
E1R22  8.2 K  [R0402]  69.15 94.23 0 top
E1R24  1 K  [R0402]  72.01 89.92 90 top
E1R25  1 K  [R0402]  71.06 89.92 90 top
E1R26  1 K  [R0402]  82.22 91.11 180 top
E1R27  1 K  [R0402]  73.79 87.12 270 top
E1R28  1 K  [R0402]  72.83 87.12 270 top
E1R29  1 K  [R0402]  71.88 87.12 270 top
E1R30  1 K  [R0402]  70.93 87.12 270 top
E1R31  1 K  [R0402]  69.98 87.12 270 top
E1U1  RTL8261BE  [QFN68-0800-0400-VIA-10-PH10]  76.2 95.89 270 top
EC16  0.1 UF/16V  [C0402]  105.03 91.31 0 top
EC17  0.1 UF/16V  [C0402]  107.42 100.08 135 top
EC18  0.1 UF/16V  [C0402]  101.73 84.07 90 bottom
EC19  0.1 UF/16V  [C0402]  128.4 90.93 90 top
EC20  0.1 UF/16V  [C0402]  131.19 95.38 90 bottom
EC21  0.1 UF/16V  [C0402]  119.63 100.71 90 top
EC22  0.1 UF/16V  [C0402]  124.97 85.85 0 bottom
EC300  33 PF/50V  [C0402]  83.34 99.09 270 top
EC301  33 PF/50V  [C0402]  83.34 97.36 90 top
EC334  0.1 UF/10V  [C0201]  80.37 89.11 90 top
EC335  0.1 UF/10V  [C0201]  79.76 89.11 90 top
EC340  0.1 UF/10V  [C0201]  68.9 101.22 180 top
ER331  4.7 K  [R0402]  85.45 92.97 180 top
ER359  0 OHM  [R0402]  77.34 88.52 90 top
ER360  0 OHM  [R0402]  78.3 88.52 90 top
EY300  S3225A-050000-F19-CYS-1AMA  [XTALS-0320X0250-YOKE]  85.55 98.35 90 top
F1  1206L150THWR  [FUSES-1206L]  47.62 128.46 270 top
F2  1206L150THWR  [FUSES-1206L]  49.59 133.99 180 bottom
F3  1206L150THWR  [FUSES-1206L]  49.66 137.54 0 bottom
F4  1206L150THWR  [FUSES-1206L]  41.15 142.3 0 top
FB5  BLM15AX601SN1D  [FILTS-0402]  115.44 52.35 180 bottom
FB6  BLM15AX601SN1D  [FILTS-0402]  113.79 53.4 180 bottom
FB7  BLM15AX601SN1D  [FILTS-0402]  106.05 57.98 270 bottom
FB8  BLM15AG100SN1D  [FILTS-0402]  103 55.82 270 bottom
FB9  BLM15AG100SN1D  [FILTS-0402]  95.25 53.78 0 bottom
FB10  BLM15AX601SN1D  [FILTS-0402]  104.33 56.77 270 bottom
FB12  BLM15AG100SN1D  [FILTS-0402]  115.7 50.99 270 bottom
FB13  BLM15AX601SN1D  [FILTS-0402]  101.47 43.81 0 bottom
FB14  BLM15AX102SN1D  [L0402]  107.96 56.48 180 bottom
FB15  BLM15AX601SN1D  [FILTS-0402]  111.89 54.58 180 bottom
H01  Screw Hole  [VIA217P-393P]  8 149.79 0 top
H02  Screw Hole  [VIA217P-393P]  8 15.79 0 top
H03  Screw Hole  [VIA217P-393P]  142 149.79 0 top
H04  Screw Hole  [VIA217P-393P]  142 15.79 0 top
J1  02040-01G059  [SIP5-02040-01G059]  142.94 89.79 270 top
J7  PHE6T0-104L4  [SIP4-PHE6T0-104L4]  143.38 51.56 270 top
L65  33 uH/2A rms  [LS-UPIF06XXW]  29.34 120.84 90 top
L600  BLM15EG121SN1D  [FILTS-0402]  57.28 38.67 270 top
L601  47 NH/300mA  [L0402-1]  56.96 35.75 270 top
L602  BLM15EG121SN1D  [FILTS-0402]  56.87 34.3 270 bottom
L603  47 NH/300mA  [L0402-1]  56.96 34.16 90 top
L604  0 OHM  [R0603]  51.42 29.81 90 bottom
L605  33 uH/0.43A  [LS-SWPA30]  65.07 25.02 180 top
L606  0 OHM  [R0603]  49.39 30.42 0 bottom
L607  0 OHM  [R0603]  64.59 31.85 180 top
L611  0 OHM  [R0603]  66.29 29.1 270 top
L612  0 OHM  [R0603]  46.99 35.18 90 bottom
L912  0.47 uH/6A Isat  [LS-TMIM2016]  32.26 112.2 0 top
NOREF  -  []  77.29 104.27 45 top
NOREF#2  VAL*  [unnamed#2]  10.79 160.02 0 top
NOREF#3  -  []  75.69 111.44 45 top
NOREF#4  -  []  -101.6 -76.2 0 top
NOREF#5  VAL*  [unnamed#2]  11 -5 180 top
NOREF#6  VAL*  [unnamed#2]  297 175 0 top
NOREF#7  -  []  126.75 109.98 45 top
NOREF#8  -  []  151 35 90 top
NOREF#9  -  []  0.64 -42.37 0 top
NOREF#10  VAL*  [unnamed#2]  11 175 180 top
NOREF#11  -  []  225 -1 0 top
NOREF#12  -  []  98.86 108.36 45 top
NOREF#13  -  []  175 -1 0 top
NOREF#14  -  []  73 -1 0 top
NOREF#15  -  []  127 171 0 top
NOREF#16  -  []  79.71 111.4 45 top
NOREF#17  -  []  162.99 -13.08 0 top
NOREF#18  -  []  71.69 111.44 45 top
NOREF#19  -  []  0.45 -10 90 top
NOREF#20  -  []  1.25 -10 90 top
NOREF#21  VAL*  [unnamed#2]  135.89 8.89 0 top
NOREF#22  -  []  72.9 103.38 45 top
NOREF#23  -  []  77.47 83.67 45 top
NOREF#24  -  []  127 -1 0 top
NOREF#25  -  []  117.86 73.18 225 top
NOREF#26  -  []  114.12 108.43 45 top
NOREF#27  VAL*  [unnamed#2]  5 -5 180 top
NOREF#28  -  []  79.78 83.64 45 top
NOREF#29  -  []  75.34 103.33 45 top
NOREF#30  -  []  65.41 -13.16 0 top
NOREF#31  -  []  108.03 108.46 45 top
NOREF#32  -  []  0 172 90 top
NOREF#33  -  []  118.54 -13.08 0 top
NOREF#34  VAL*  [unnamed#2]  291 175 0 top
NOREF#35  -  []  23 171 0 top
NOREF#36  -  []  56 171 0 top
NOREF#37  -  []  21.35 0 90 top
NOREF#38  VAL*  [unnamed#2]  139.45 157.23 0 top
NOREF#39  -  []  114.71 68.71 225 top
NOREF#40  -  []  -5 -18 0 top
NOREF#41  -  []  0 0 0 top
NOREF#42  -  []  110.82 71.17 135 top
NOREF#43  -  []  0 145.83 0 top
NOREF#44  -  []  111.15 108.74 45 top
NOREF#45  -  []  116.84 69.47 225 top
NOREF#46  -  []  79.35 104.34 45 top
NOREF#47  -  []  308 -14 0 top
NOREF#48  -  []  93.45 108.41 45 top
NOREF#49  -  []  101.93 108.23 45 top
NOREF#50  -  []  279 -1 0 top
NOREF#51  VAL*  [unnamed#2]  6.35 27.94 0 top
NOREF#52  -  []  130.63 109.98 45 top
NOREF#53  -  []  -5 189 0 top
NOREF#54  -  []  208 171 0 top
NOREF#55  -  []  0 180 0 top
NOREF#56  -  []  187 184 0 top
NOREF#57  -  []  122.89 109.96 45 top
NOREF#58  -  []  279 171 0 top
NOREF#59  -  []  175 171 0 top
NOREF#60  -  []  0.64 -13.16 0 top
NOREF#61  -  []  151 90 90 top
NOREF#62  VAL*  [unnamed#2]  291 -5 0 top
NOREF#63  -  []  23 -1 0 top
NOREF#64  -  []  151 145 90 top
NOREF#65  -  []  134.49 109.98 45 top
NOREF#66  -  []  95.83 108.15 45 top
NOREF#67  -  []  105.03 108.28 45 top
NOREF#68  -  []  204.27 -13.08 0 top
NOREF#69  VAL*  [unnamed#2]  5 175 180 top
NOREF#70  VAL*  [unnamed#2]  297 -5 0 top
NOREF#71  -  []  83.9 111.4 45 top
NOREF#72  -  []  161.29 -49.53 0 top
P3  ZW2J88-J260S1F  [RJ45-ZW2J88-J260S1X]  68.64 166.87 180 top
P4  ZW2J88-J260S1F  [RJ45-ZW2J88-J260S1X]  101.94 166.87 180 top
P5  ZW2J88-J260S1F  [RJ45-ZW2J88-J260S1X]  118.59 166.87 180 top
P6  ZW2J88-J260S1F  [RJ45-ZW2J88-J260S1X]  85.29 166.87 180 top
PC351  22 UF/6.3V  [C0603]  129.83 37.02 180 top
PC352  0.1 UF/16V  [C0402]  129.77 38.16 180 top
PC353  0.1 UF/16V  [C0402]  65.34 76.39 0 top
PC354  22 UF/6.3V  [C0603]  65.28 78.93 0 top
PC355  22 UF/6.3V  [C0603]  129.83 35.62 180 top
PC356  10 PF/50V  [C0201]  143.74 41.72 90 top
PC357  1 UF/50V  [C0603]  137.77 36.83 0 top
PC358  1000 PF/50V  [C0402]  138.44 41.96 90 top
PC359  6800 PF/50V  [C0603]  141.71 40.13 0 top
PC360  10 UF/50V  [C1206]  135.1 42.81 90 top
PC361  10 UF/50V  [C1206]  132.83 42.84 90 top
PC362  0.1 UF/50V  [MLCC-0120X0070]  137.12 42.7 90 top
PC363  22 UF/6.3V  [C0603]  65.28 77.53 0 top
PC364  10 PF/50V  [C0201]  56.58 77.34 180 top
PC365  1 UF/50V  [C0603]  61.85 73.53 90 top
PC366  1000 PF/50V  [C0402]  56.9 72.9 90 top
PC367  22 UF/6.3V  [C0603]  129.83 34.23 180 top
PC368  22 UF/6.3V  [C0603]  65.28 80.33 0 top
PC369  6800 PF/50V  [C0603]  58.8 76.83 90 top
PC370  10 UF/50V  [C1206]  59.25 66.93 0 top
PC371  10 UF/50V  [C1206]  59.25 69.15 0 top
PC372  0.1 UF/50V  [MLCC-0120X0070]  59.37 70.87 0 top
PC373  22 UF/6.3V  [C0603]  76.26 79.57 90 top
PC374  0.1 UF/16V  [C0402]  74.99 79.44 90 top
PC375  22 UF/6.3V  [C0603]  79.06 79.57 90 top
PC376  22 UF/6.3V  [C0603]  77.66 79.57 90 top
PC377  22 UF/6.3V  [C0603]  134.18 62.36 90 top
PC378  10 PF/50V  [C0201]  67.94 77.53 180 top
PC379  22 UF/6.3V  [C0603]  135.57 62.36 90 top
PC380  0.1 UF/16V  [C0402]  131.51 62.36 90 top
PC381  22 UF/6.3V  [C0603]  136.97 62.36 90 top
PC382  33 PF/50V  [C0402]  134.68 71.44 270 top
PC383  0.22 UF/50V  [C0603]  140.59 68.58 90 top
PC384  1 UF/50V  [C0603]  72.9 74.23 90 top
PC385  1000 PF/50V  [C0402]  67.5 73.22 90 top
PC386  10 UF/50V  [C1206]  124.9 67.5 270 top
PC387  10 UF/50V  [C1206]  127.19 67.5 270 top
PC388  0.1 UF/50V  [MLCC-0120X0070]  133.54 67.5 270 top
PC389  6800 PF/50V  [C0603]  69.98 76.9 90 top
PC390  10 UF/50V  [C1206]  70.55 66.93 0 top
PC391  10 UF/50V  [C1206]  70.55 69.22 0 top
PC392  0.1 UF/50V  [MLCC-0120X0070]  70.61 70.99 0 top
PC393  22 UF/6.3V  [C0603]  97.8 97.17 180 top
PC394  0.1 UF/16V  [C0402]  97.8 101.04 180 top
PC395  22 UF/6.3V  [C0603]  97.8 99.9 180 top
PC396  22 UF/6.3V  [C0603]  97.8 98.5 180 top
PC397  10 PF/50V  [C0201]  96.39 87.48 90 top
PC398  1 UF/50V  [C0603]  101.73 94.03 180 top
PC399  1000 PF/50V  [C0402]  100.3 89.15 270 top
PC400  6800 PF/50V  [C0603]  97.73 91 180 top
PC401  10 UF/50V  [C1206]  129.48 67.5 270 top
PC402  10 UF/50V  [C1206]  131.76 67.5 270 top
PC403  22 UF/6.3V  [C0603]  132.78 62.36 90 top
PC404  1 UF/16V  [C0402]  137.73 71.44 90 top
PC405  10 UF/50V  [C1206]  100.97 84.77 180 top
PC406  10 UF/50V  [C1206]  100.97 87.06 180 top
PC407  0.1 UF/50V  [MLCC-0120X0070]  101.73 89.41 180 top
PC430  0.1 UF/16V  [C0402]  132.78 71.44 90 top
PC484  1 UF/16V  [C0402]  141.9 38.54 270 top
PC485  1 UF/16V  [C0402]  58.04 75.37 180 bottom
PC486  1 UF/16V  [C0402]  69.34 75.5 180 bottom
PC487  1 UF/16V  [C0402]  97.68 93.09 180 top
PC677  0.1 UF/16V  [C0402]  36.26 74.36 180 top
PC679  10 UF/50V  [C1206]  40.26 71.37 0 top
PC680  10 UF/50V  [C1206]  40.26 73.6 0 top
PC681  22 UF/6.3V  [C0603]  46.67 74.42 180 top
PC682  1 UF/16V  [C0402]  36.26 79.44 180 top
PC683  33 PF/50V  [C0402]  36.26 77.34 0 top
PC684  22 UF/6.3V  [C0603]  46.67 75.82 180 top
PC685  22 UF/6.3V  [C0603]  46.67 77.22 180 top
PC686  22 UF/6.3V  [C0603]  46.67 78.61 180 top
PC687  0.1 UF/16V  [C0402]  46.61 73.28 180 top
PC688  10 UF/50V  [C1206]  40.26 66.93 0 top
PC689  0.1 UF/50V  [MLCC-0120X0070]  40.2 75.31 0 top
PC690  10 UF/50V  [C1206]  40.26 69.15 0 top
PC691  0.22 UF/50V  [C0603]  39.05 82.3 180 top
PL180  2.2 uH/2.95A  [LRS-ATNR4030]  134.06 37.11 90 top
PL181  1.5 uH/3.4A Isat  [LS-AMPI2520]  63.94 73.91 90 top
PL182  3.3 uH/3.4A  [LRS-ATNR50XX]  76.71 74.87 0 top
PL183  1.5 uH/3.4A Isat  [LS-AMPI2520]  101.19 97.61 180 top
PL333  1 uH/5.67A Irms  [LRS-ATNR6028]  141.16 63.75 180 top
PL353  3.3uH/7.5A rms  [LS-MWSA06XXS]  44.89 82.93 0 top
PR113  10 K  [R0402]  143.87 38.54 90 top
PR337  59 K  [R0402]  141.96 41.72 270 top
PR338  82 K  [R0402]  56.52 75.44 0 top
PR339  40.2 K  [R0402]  142.91 41.72 90 top
PR340  20 K  [R0402]  56.52 76.45 180 top
PR341  40.2 K  [R0402]  67.94 76.64 180 top
PR342  30 K  [R0402]  67.94 75.63 0 top
PR343  15 K  [R0402]  97.28 87.6 90 top
PR344  75 K  [R0402]  141.01 41.72 90 top
PR345  20 OHM  [R0402]  139.61 37.27 270 top
PR346  20 OHM  [R0402]  61.15 75.63 0 top
PR347  120 K  [R0402]  56.52 74.42 180 top
PR348  20 OHM  [R0402]  72.07 76.14 0 top
PR349  36 K  [R0402]  67.94 74.61 180 top
PR350  20 OHM  [R0402]  99.54 94.03 0 top
PR351  40.2 K  [R0402]  135.64 71.44 270 top
PR352  20 K  [R0402]  133.73 71.44 90 top
PR353  80.6 K  [R0402]  136.59 71.44 90 top
PR354  82 K  [R0402]  97.03 89.43 90 top
PR355  0 OHM  [R0402]  139 69.28 0 top
PR356  120 K  [R0402]  97.97 89.43 270 top
PR380  100 K  [R0402]  131.25 70.99 0 top
PR383  100 K  [R0402]  137.16 65.34 270 top
PR386  0 OHM  [R0805]  122.8 67.41 90 top
PR387  0 OHM  [R1206]  128.68 61.33 0 top
PR388  0 OHM  [R1206]  128.68 59.04 0 top
PR460  100 K  [R0402]  142.85 38.54 90 top
PR461  10 K  [R0402]  140.94 38.54 270 top
PR462  100 K  [R0402]  139.37 41.96 90 top
PR463  100 K  [R0402]  58.48 73.03 90 bottom
PR464  100 K  [R0402]  55.94 72.9 90 top
PR465  10 K  [R0402]  58.04 74.42 180 bottom
PR466  100 K  [R0402]  69.79 73.15 90 bottom
PR467  100 K  [R0402]  67.5 71.37 270 top
PR468  10 K  [R0402]  69.34 74.55 180 bottom
PR469  100 K  [R0402]  97.68 94.04 0 top
PR470  100 K  [R0402]  99.36 89.15 270 top
PR471  10 K  [R0402]  97.68 92.14 180 top
PR607  10 K  [R0402]  36.26 75.31 180 top
PR608  40.2 K  [R0402]  36.26 76.33 0 top
PR609  8.87 K  [R0402]  36.26 78.3 180 top
PR610  100 K  [R0402]  42.35 78.87 0 top
PR611  0 OHM  [R0805]  39.05 64.26 90 top
PR612  0 OHM  [R1206]  51.12 73.79 180 top
PR613  0 OHM  [R0402]  38.42 80.64 90 top
PR614  0 OHM  [R1206]  51.12 78.36 180 top
PR615  100 K  [R0402]  36.7 72.96 90 top
PR619  0 OHM  [R1206]  51.12 76.07 180 top
PU10  MP2384GG-Z  [QFN11-0200-0500]  136.53 68.14 0 top
PU14  MP2331GTL-Z  [SOT-583-MPS]  138.79 39.43 270 top
PU15  MP2331GTL-Z  [SOT-583-MPS]  58.99 73.72 0 top
PU16  MP2331GTL-Z  [SOT-583-MPS]  70.23 73.85 0 top
PU17  MP2331GTL-Z  [SOT-583-MPS]  100.58 91.25 90 top
PU23  MP3910GK-Z  [SOP10-0490-0500-3]  29.34 67.06 180 top
PU30  MP4541GN-Z  [SOP8-0600-1270-VIA-2]  35.43 123.32 180 top
PU40  MP2329GG-Z  [QFN11-0200-0500]  39.56 78.23 90 top
PU902  RT9080N-08GJ5  [SOT-23-5-RICHTEK]  130.72 49.7 90 top
PU908  LP5907MFX-18/NOP8  [SOT-23-5-TI-1]  130.72 53.99 90 top
Q1  LMBT3904LT1G  [SOT-23-EBC]  32.64 12.13 180 top
Q2  LMBT3904LT1G  [SOT-23-EBC]  37.78 12.13 180 top
Q3  LMBT3904LT1G  [SOT-23-EBC]  43.05 12.19 180 top
Q4  LMBT3904LT1G  [SOT-23-EBC]  80.52 12.13 180 top
Q5  LMBT3904LT1G  [SOT-23-EBC]  75.44 12.13 180 top
Q6  LMBT3904LT1G  [SOT-23-EBC]  49.02 12.13 180 top
Q7  LMBT3904LT1G  [SOT-23-EBC]  54.61 12.13 180 top
Q8  LMBT3904LT1G  [SOT-23-EBC]  59.82 12.13 180 top
Q9  LMBT3904LT1G  [SOT-23-EBC]  65.15 12.13 180 top
Q10  LMBT3904LT1G  [SOT-23-EBC]  70.36 12.19 180 top
Q600  SMS123-C  [SOT-23-SGD]  61.25 22.94 90 bottom
Q601  LBC856BDW1T1G  [SOT-363-LRC]  54.23 24.57 270 top
Q602  SMS123-C  [SOT-23-SGD]  62.48 28.89 270 bottom
Q603  LBC856BDW1T1G  [SOT-363-LRC]  54.36 23.94 270 bottom
Q802  MTN4410Q8-0-T3-G  [SOP8-0600-1270-9]  23.94 155.32 0 top
Q803  SSD50N10-C/100V/30A  [TO-252-GDS-SECOS]  9.27 64.64 0 top
Q804  SSPR18N10-C  [SON8-0330-0650-PAD-3]  44.32 127.57 270 top
Q805  SSPR18N10-C  [SON8-0330-0650-PAD-3]  44.2 133.22 0 top
Q806  SSPR18N10-C  [SON8-0330-0650-PAD-3]  44.2 136.91 0 top
Q807  SSPR18N10-C  [SON8-0330-0650-PAD-3]  35.43 142.3 90 top
Q808  MMBTA06  [SOT-23-EBC]  34.67 102.23 0 top
R27  22 OHM  [R0402]  138.05 51.63 180 top
R28  5.9 K  [R0402]  98.23 48.58 90 bottom
R66  60.4 K  [R0402]  96.84 48.96 0 bottom
R68  10 K  [R0402]  113.94 47.57 0 bottom
R83  10 K  [R0402]  122.81 54.28 0 top
R89  10 K  [R0402]  121.41 53.77 90 top
R91  4.7 K  [R0402]  33.27 134.37 270 bottom
R93  10 K  [R0402]  121.98 48.9 0 top
R94  10 K  [R0402]  122.43 46.67 90 top
R105  49.9 OHM/1%  [R0402]  120.17 26.78 180 bottom
R106  49.9 OHM/1%  [R0402]  121.86 24.4 180 bottom
R107  49.9 OHM/1%  [R0402]  119.72 28.05 180 bottom
R108  49.9 OHM/1%  [R0402]  121.86 26.46 180 bottom
R109  49.9 OHM/1%  [R0402]  123.69 26.01 180 bottom
R110  49.9 OHM/1%  [R0402]  121.86 27.65 180 bottom
R111  49.9 OHM/1%  [R0402]  121.86 28.76 180 bottom
R112  49.9 OHM/1%  [R0402]  117.42 32.25 270 bottom
R113  49.9 OHM/1%  [R0402]  119.8 29.08 180 bottom
R114  49.9 OHM/1%  [R0402]  118.12 30.43 270 bottom
R115  49.9 OHM/1%  [R0402]  123.69 19.63 180 bottom
R116  49.9 OHM/1%  [R0402]  118.61 32.25 270 bottom
R118  49.9 OHM/1%  [R0402]  121.79 21.27 180 bottom
R119  49.9 OHM/1%  [R0402]  116.94 30.51 270 bottom
R120  49.9 OHM/1%  [R0402]  119.09 30.43 270 bottom
R121  49.9 OHM/1%  [R0402]  121.78 20.37 180 bottom
R122  49.9 OHM/1%  [R0402]  123.69 22.81 180 bottom
R123  49.9 OHM/1%  [R0402]  121.86 25.43 180 bottom
R124  49.9 OHM/1%  [R0402]  123.69 23.92 180 bottom
R125  49.9 OHM/1%  [R0402]  123.69 25.03 180 bottom
R126  49.9 OHM/1%  [R0402]  121.79 19.16 180 bottom
R127  49.9 OHM/1%  [R0402]  123.69 20.66 180 bottom
R128  49.9 OHM/1%  [R0402]  121.86 22.25 180 bottom
R130  49.9 OHM/1%  [R0402]  121.86 23.36 180 bottom
R131  4.7 K/5%  [R0402]  105.54 44.6 90 bottom
R132  4.7 K/5%  [R0402]  106.43 44.63 90 bottom
R133  100 OHM/1%  [R0201]  114.2 20.35 225 bottom
R135  240 OHM/1%  [R0402]  108.03 22.91 90 top
R136  240 OHM/1%  [R0402]  87.76 25.65 90 top
R151  200 OHM/1%  [R0402]  113.28 57.28 225 top
R152  10 K  [R0402]  95.12 56.9 0 top
R154  200 OHM/1%  [R0402]  103.31 58.42 90 top
R155  10 K  [R0402]  76.2 49.85 180 top
R156  2.7 K  [R0402]  76.2 48.83 0 top
R172  0 OHM  [R0402]  91.76 49.47 45 top
R173  1 K  [R0402]  32.58 15.05 90 top
R174  240 OHM/1%  [R0402]  107.29 44.63 270 bottom
R175  1 K  [R0402]  37.78 15.05 270 top
R176  1 K  [R0402]  80.52 15.11 270 top
R177  1 K  [R0402]  75.44 15.11 270 top
R178  1 K  [R0402]  49.02 15.05 270 top
R179  1 K  [R0402]  42.99 15.05 90 top
R180  1 K  [R0402]  59.75 15.05 270 top
R181  10 K  [R0402]  80.07 49.85 0 top
R182  2.7 K  [R0402]  80.07 48.83 180 top
R183  10 K  [R0402]  97.22 58.42 270 top
R184  2.7 K  [R0402]  96.27 58.42 90 top
R185  10 K  [R0402]  122 51.94 180 top
R186  2.7 K  [R0402]  120.17 51.94 180 top
R187  10 K  [R0402]  122 50.98 180 top
R188  2.7 K  [R0402]  119.51 50.98 180 top
R189  1 K  [R0402]  54.55 15.05 90 top
R190  2.7 K  [R0402]  95.12 55.94 180 top
R191  10 K  [R0402]  120.42 53.77 270 top
R192  2.7 K  [R0402]  119.46 53.77 90 top
R193  10 K  [R0402]  94.36 58.42 270 top
R194  2.7 K  [R0402]  95.31 58.42 90 top
R195  1 K  [R0402]  70.29 15.11 270 top
R196  1 K  [R0402]  64.96 15.11 90 top
R197  0 OHM  [R0201]  91.06 51.37 0 top
R198  0 OHM  [R0201]  91.06 50.67 0 top
R199  22 K/1%  [R0402]  98.86 57 0 bottom
R200  0 OHM  [R0402]  111.81 48.54 0 bottom
R203  4.7 K  [R0402]  113.94 48.54 180 bottom
R229  1.5 K  [R0402]  100.08 58.42 270 top
R230  1.5 K  [R0402]  101.35 58.42 270 top
R231  10 K  [R0402]  99.12 58.42 270 top
R232  10 K  [R0402]  107.82 59.05 270 top
R233  10 K  [R0402]  98.17 58.42 270 top
R234  1.5 K  [R0402]  109.66 76.83 90 top
R235  1.5 K  [R0402]  109.66 78.68 270 top
R239  75 OHM  [R0603]  132.72 135.13 90 top
R240  75 OHM  [R0603]  128.91 135.13 90 top
R241  75 OHM  [R0603]  113.41 136.14 90 top
R242  75 OHM  [R0603]  125.09 135.13 90 top
R243  75 OHM  [R0603]  120.52 135.13 90 top
R244  75 OHM  [R0603]  94.61 136.14 90 top
R245  75 OHM  [R0603]  103.89 136.14 90 top
R246  75 OHM  [R0603]  109.86 136.14 90 top
R247  75 OHM  [R0603]  106.81 135.25 90 top
R248  75 OHM  [R0603]  90.55 135.25 90 top
R249  75 OHM  [R0603]  100.33 135.25 90 top
R250  75 OHM  [R0603]  97.66 135.25 90 top
R251  75 OHM  [R0603]  70.1 135.25 90 top
R252  75 OHM  [R0603]  73.41 135.25 90 top
R253  75 OHM  [R0603]  77.72 135.25 90 top
R254  0 OHM  [R0402]  113.41 56.08 180 bottom
R255  0 OHM  [R0402]  113.79 54.23 180 top
R256  0 OHM  [R0402]  109.03 54.61 0 bottom
R257  0 OHM  [R0402]  110.54 53.34 180 bottom
R258  10 K  [R0402]  102.36 58.42 270 top
R261  75 OHM  [R0603]  81.53 135.25 90 top
R274  1 K  [R0402]  122.81 53.31 180 top
R277  10 K  [R0402]  108.78 59.05 270 top
R278  0 OHM  [R0402]  100.01 46.48 270 bottom
R350  2.2 K  [R0402]  23.5 143.7 180 top
R351  1 K  [R0402]  25.34 143.7 0 top
R352  2.2 K  [R0402]  23.88 134.81 270 top
R353  1 K  [R0402]  25.15 134.81 270 top
R357  0 OHM  [R0402]  35.18 157.73 90 top
R358  0 OHM  [R0402]  34.23 157.73 90 top
R495  0 OHM  [R0603]  28.51 131.95 90 top
R496  0 OHM  [R0805]  50.42 118.49 180 top
R497  100 K  [R0603]  42.35 124.02 90 top
R498  23.2 K  [R0603]  32.19 128.46 270 top
R499  300 OHM  [R0603]  29.21 129.92 0 top
R500  4.7 K  [R0603]  40.96 124.02 270 top
R501  80.6 K  [R0603]  34.86 128.46 90 top
R502  10 K  [R0603]  33.53 128.46 90 top
R604  4.7 K  [R0402]  65.53 38.29 180 top
R605  4.7 K  [R0402]  61.85 30.5 180 top
R606  4.7 K  [R0402]  65.53 37.34 180 top
R610  0 OHM  [R0402]  48.51 38.58 0 top
R611  0 OHM  [R0402]  112.71 59.05 270 top
R612  0 OHM  [R0402]  111.76 59.05 270 top
R613  4.7 K  [R0402]  63.82 38.67 90 top
R614  150 OHM/1%  [R0402]  56.39 38.67 270 top
R615  0 OHM  [R0402]  116.01 59.05 270 top
R616  0 OHM  [R0402]  116.97 59.05 270 top
R617  0 OHM  [R0402]  64.2 36.32 180 top
R620  150 OHM/1%  [R0402]  55.92 34.3 270 bottom
R621  4.7 K  [R0402]  106.68 59.05 90 top
R623  220 OHM/5%  [R0402]  62.1 39.12 270 top
R629  4.7 K  [R0402]  47.62 26.59 90 bottom
R630  4.7 K  [R0402]  47.61 24.81 270 bottom
R633  0 OHM  [R0402]  48.94 26.16 0 bottom
R635  100 OHM/1%  [R0402]  60.13 27.18 90 bottom
R636  20 K/1%  [R0402]  62.69 26.63 90 top
R637  100 OHM/1%  [R0402]  56.52 24.77 180 top
R638  100 OHM/1%  [R0402]  56.52 23.88 180 top
R639  0 OHM  [R0402]  48.94 25.21 0 bottom
R641  4.7 K  [R0402]  44.47 22.35 180 bottom
R642  0 OHM  [R0402]  50.29 24.81 90 bottom
R644  0 OHM  [R0402]  50.29 26.56 270 bottom
R647  100 K/5%  [R0402]  64.07 24.21 180 bottom
R648  180 K/1%  [R0402]  62.39 36.16 180 bottom
R651  0 OHM  [R0402]  62.39 35.21 180 bottom
R652  0 OHM  [R0201]  63.28 26.57 180 bottom
R655  0 OHM  [R0402]  56.2 23.89 270 bottom
R656  0 OHM  [R0402]  51.82 23.75 90 bottom
R660  470 OHM/1%  [R0402]  56.72 25.65 0 bottom
R662  470 OHM/1%  [R0402]  55 25.65 0 bottom
R664  NC  [R0402]  61.85 37.12 180 bottom
R665  0 OHM/5%  [R0402]  55.86 25.65 180 bottom
R699  4.7 K  [R0402]  65.53 39.24 180 top
R800  820 OHM  [R0402]  35.12 10.92 90 top
R801  300 OHM  [R0402]  40.26 10.92 90 top
R802  820 OHM  [R0402]  45.53 10.99 90 top
R803  56 OHM  [R0402]  77.98 10.92 90 top
R804  820 OHM  [R0402]  83.06 10.92 90 top
R805  300 OHM  [R0402]  51.5 10.92 90 top
R806  820 OHM  [R0402]  57.15 10.92 90 top
R807  300 OHM  [R0402]  62.36 10.92 90 top
R808  820 OHM  [R0402]  67.63 10.92 90 top
R809  10 K  [R0402]  49.66 156.78 180 top
R810  130 OHM/5%  [R0402]  50.1 160.08 90 top
R811  300 OHM  [R0402]  72.83 10.99 90 top
R830  4.7 K  [R0402]  35.75 15.05 90 top
R831  4.7 K  [R0402]  30.54 15.05 90 top
R832  4.7 K  [R0402]  78.49 15.11 90 top
R833  4.7 K  [R0402]  46.16 15.05 90 top
R834  4.7 K  [R0402]  73.34 15.11 90 top
R835  4.7 K  [R0402]  40.96 15.05 90 top
R836  4.7 K  [R0402]  52.51 15.05 90 top
R837  4.7 K  [R0402]  57.72 15.05 90 top
R838  4.7 K  [R0402]  62.93 15.11 90 top
R839  4.7 K  [R0402]  68.26 15.11 90 top
R905  4.7 K  [R0603]  54.86 81.34 0 top
R916  4.7 K  [R0603]  125.96 62.69 90 top
R918  0 OHM  [R1206]  129.54 21.11 90 top
R928  4.7 K  [R0603]  97.05 43.98 270 bottom
R936  4.7 K  [R0603]  133.55 31.09 90 top
